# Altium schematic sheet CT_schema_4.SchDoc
size 300 x 177 mm
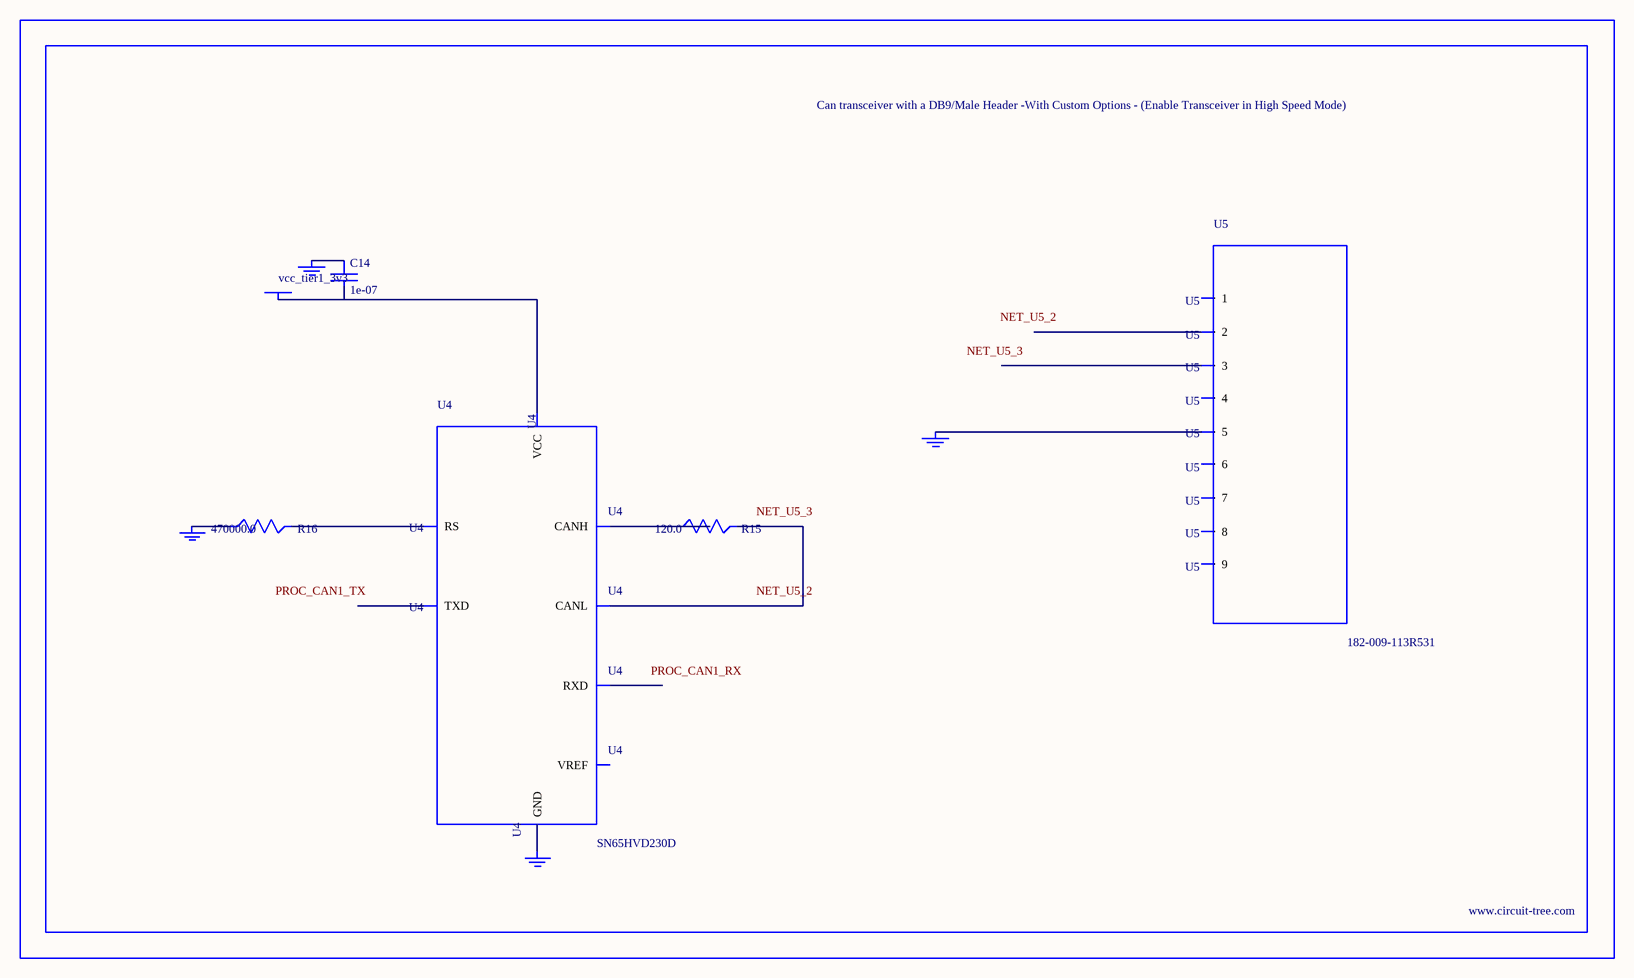
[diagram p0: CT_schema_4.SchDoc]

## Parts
BORDER3  (no value)
C14  1e-07  [C0402]
GND_INSTANCE_3_0  (no value)
GND_INSTANCE_3_1  (no value)
GND_INSTANCE_3_2  (no value)
GND_INSTANCE_3_3  (no value)
POWER_INSTANCE_3_0  vcc_tier1_3v3
R15  120.0  [R0603]
R16  470000.0  [R0603]
U4  SN65HVD230D  [SOIC-8]
U5  182-009-113R531  [182-009-MALE]

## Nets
NetC14_1: C14.1 GND_INSTANCE_3_0.0(GND)
NetC14_2: C14.2 POWER_INSTANCE_3_0.0(PWR) U4.3(VCC)
NetGND_INSTANCE_3_1_0: GND_INSTANCE_3_1.0(GND) R16.1
NetGND_INSTANCE_3_2_0: GND_INSTANCE_3_2.0(GND) U4.2(GND)
NetGND_INSTANCE_3_3_0: GND_INSTANCE_3_3.0(GND) U5.5
NetR15_1: R15.1 U4.7(CANH)
NetR15_2: R15.2 U4.6(CANL)
NetR16_2: R16.2 U4.8(RS)

Not connected (* = marked no-connect by the designer): U4 1(TXD) 4(RXD) 5(VREF); U5 1 2 3 4 6 7 8 9

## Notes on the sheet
- Labels drawn without touching a wire or pin: NET_U5_2, NET_U5_3, PROC_CAN1_RX, PROC_CAN1_TX

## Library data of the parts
BORDER3 = BORDER_PAGE3
C14 = C0402C104K3RACTU
GND_INSTANCE_3_0-GND_INSTANCE_3_3 = GND
POWER_INSTANCE_3_0 = PWR
R15 = RC0603JR-07120RL
R16 = RC0603JR-07470KL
